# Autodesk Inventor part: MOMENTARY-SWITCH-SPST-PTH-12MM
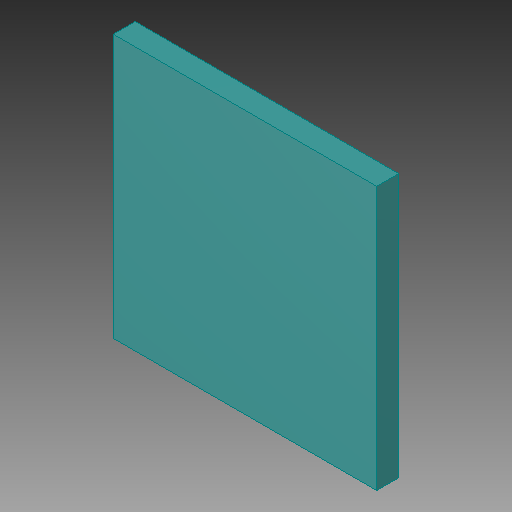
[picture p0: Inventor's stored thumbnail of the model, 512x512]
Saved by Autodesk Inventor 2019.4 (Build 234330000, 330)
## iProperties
Created: 2019-11
Part Number: MOMENTARY-SWITCH-SPST-PTH-12MM
Material: Generic
Document SubType Name: Modeling
Designer: Willist
Density: 1 g/cm^3
Appearance: TACTILE_SWITCH_PTH_12MM, MOMENTARY-SWITCH-SPST-PTH-12MM
Author: Willist
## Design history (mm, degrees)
sketch "TACTILE_SWITCH_PTH_12MM, MOMENTARY-SWITCH-SPST-PTH-12MM_3"
  geometry: L1 (-6, 6)-(6, 6); L2 (6, 6)-(6, -6); L3 (6, -6)-(-6, -6); L4 (-6, -6)-(-6, 6)
  constraints: 8 end point
extrude "Extrusion1" join sketch "TACTILE_SWITCH_PTH_12MM, MOMENTARY-SWITCH-SPST-PTH-12MM_3" distance "d0" = 1; taper "d1" = 0 deg
body "Solid1"
